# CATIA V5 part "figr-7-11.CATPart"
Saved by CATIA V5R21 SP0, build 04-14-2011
Part number: Part1
Bounding box of the stored display mesh (mm): x -50 to 50, y -62.5 to 112.5, z 0 to 100
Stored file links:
  D:\CATIA V5R21 E-RESOURCES\CATIA-V5R21\catia-v5r21-prt\c07-catia-v5r20-prt\c07-catia-v5r21-figr-7-11.CATPart
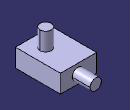
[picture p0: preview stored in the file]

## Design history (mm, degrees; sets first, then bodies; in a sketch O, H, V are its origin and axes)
Body1 (main body)
  Sketch1 on xy-plane, origin (0, 0, 0), H (1, 0, 0), V (0, 1, 0)
    line L1 (-50, 62.5) -> (50, 62.5)
    line L2 (50, 62.5) -> (50, -62.5)
    line L3 (50, -62.5) -> (-50, -62.5)
    line L4 (-50, -62.5) -> (-50, 62.5)
    axis line L5 (50, -62.5) -> (-50, 62.5)
    length L3 = 100
    length L2 = 125
    horizontal: L1 H, L3 H
    vertical: L2 V, L4 V
    midpoint: O L5
  Pad1: profile Sketch1, direction (0, 0, 1), length 50
  Sketch2 on face of Pad1, origin (0, 0, 50), H (1, 0, 0), V (0, 1, 0)
    circle A1 centre (8.7691, -19.7725) radius 15.5717
  Pad2: profile Sketch2, direction (0, 0, 1), length 50
  Sketch3 on face of Pad1, origin (0, 62.5, 112.5), H (1, 0, 0), V (0, 0, -1)
    circle A1 centre (2.1924, 87.7667) radius 15.5717
  Pad3: profile Sketch3, direction (0, 1, 0), length 50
